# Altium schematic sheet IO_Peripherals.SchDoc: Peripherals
size A4; Date: Not used; ApprovedBy: Not used; CheckedBy: Not used; Author: Not used; CompanyName: STMicroelectronics; DrawnBy: Not used; Engineer: Not used; Organization: Not used; Address1: Not used; Address2: Not used; Address3: Not used; Address4: Not used; Revision: Not used; SheetNumber: 7; SheetTotal: 8
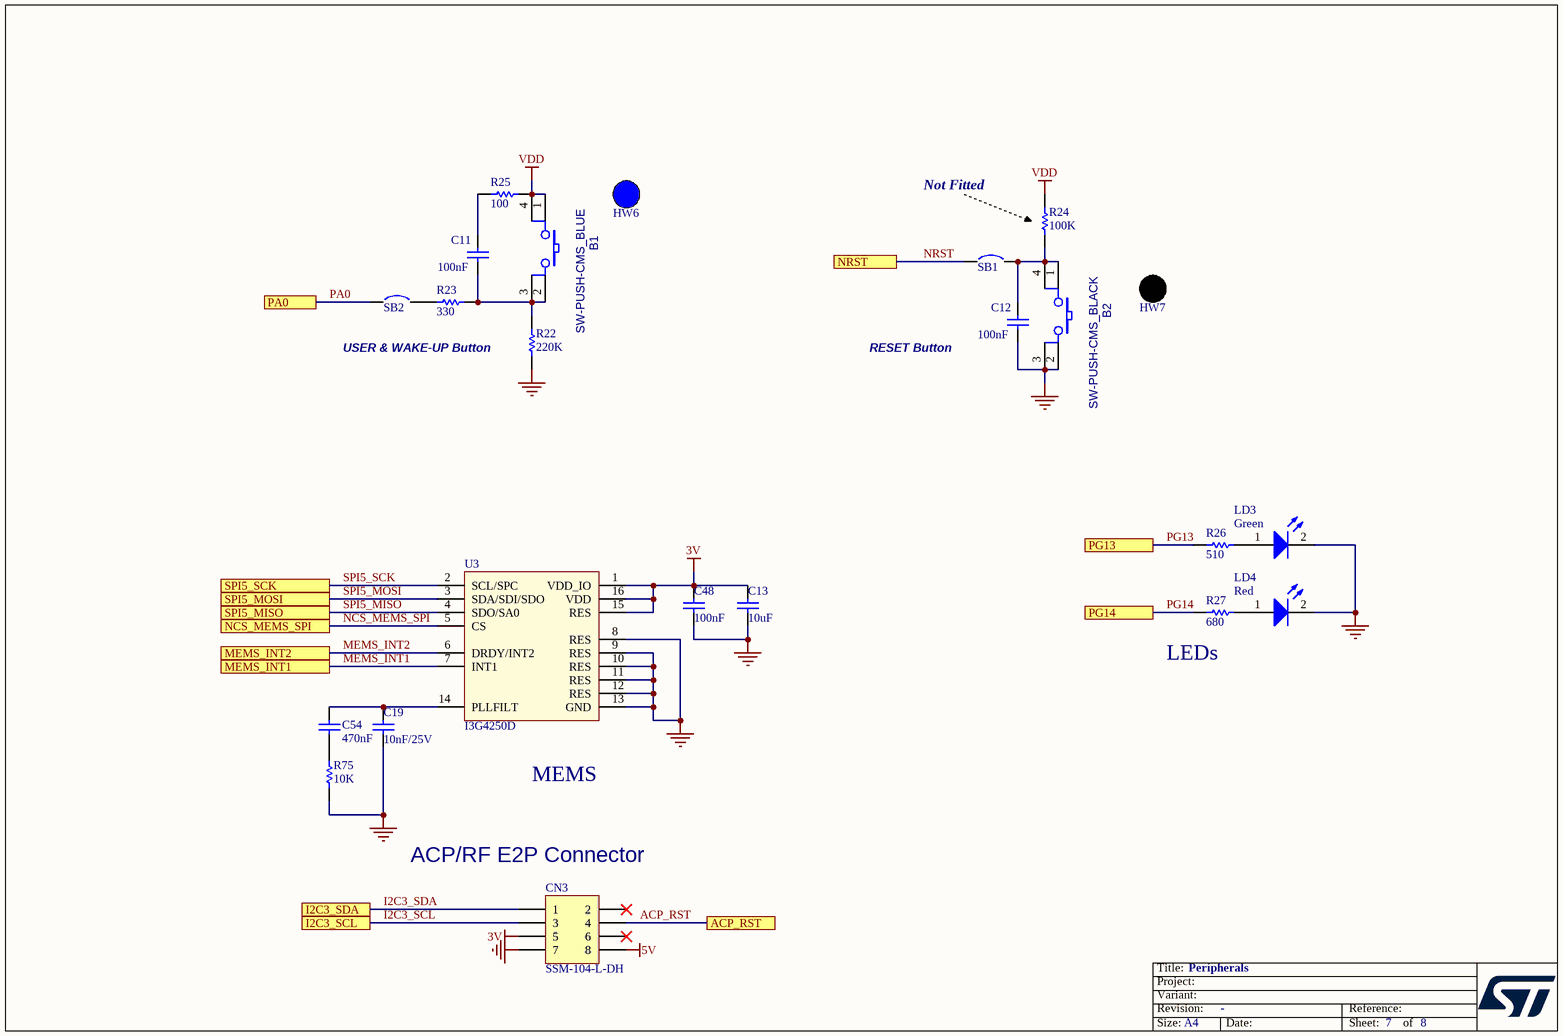
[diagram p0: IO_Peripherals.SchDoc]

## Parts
B1  SW-PUSH-CMS_BLUE  [BP1CMS]
B2  SW-PUSH-CMS_BLACK  [BP1CMS]
C11  100nF  [0402C]
C12  100nF  [0402C]
C13  10uF  [0603C]
C19  10nF/25V  [0603C]
C48  100nF  [0402C]
C54  value 470nF  [C0603]  (hidden comment: Capacitor)
CN3  SSM-104-L-DH  [SSM-104-L-DH]
HW6  BUTTON_HAT_BLUE  (value not drawn)  (mechanical)
HW7  BUTTON_HAT_BLACK  (value not drawn)  (mechanical)
LD3  Green  [0603D]
LD4  Red  [0603D]
R22  220K  [0402R]
R23  330  [0402R]
R24  100K  [0402R]
R25  100  [0402R]
R26  510  [0603R]
R27  680  [0603R]
R75  10K  [0402R]
SB1  Circuit Breaker  [JP2_SMD]  (value not drawn)
SB2  Circuit Breaker  [JP2_SMD]  (value not drawn)
U3  I3G4250D  [ICC_LGA16_4X4_P065_H1P1]

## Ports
ACP_RST, I2C3_SCL, I2C3_SDA, MEMS_INT1, MEMS_INT2, NCS_MEMS_SPI, NRST, PA0, PG13, PG14, SPI5_MISO, SPI5_MOSI, SPI5_SCK

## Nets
3V: C13.2 C48.2 CN3.5 U3.1(VDD_IO) U3.15(RES) U3.16(VDD)
5V: CN3.8
GND: B2.2 B2.3 C12.1 C13.1 C19.1 C48.1 CN3.7 LD3.2(K) LD4.2(K) R22.1 R75.1 U3.8(RES) U3.9(RES) U3.10(RES) U3.11(RES) U3.12(RES) U3.13(GND)
VDD: B1.1 B1.4 R24.2 R25.2
ACP_RST: CN3.4 ; port ACP_RST
I2C3_SCL: CN3.3 ; port I2C3_SCL
I2C3_SDA: CN3.1 ; port I2C3_SDA
MEMS_INT1: U3.7(INT1) ; port MEMS_INT1
MEMS_INT2: U3.6(DRDY/INT2) ; port MEMS_INT2
NCS_MEMS_SPI: U3.5(CS) ; port NCS_MEMS_SPI
NRST: SB1.1 ; port NRST
PA0: SB2.1 ; port PA0
PG13: R26.1 ; port PG13
PG14: R27.1 ; port PG14
SPI5_MISO: U3.4(SDO/SA0) ; port SPI5_MISO
SPI5_MOSI: U3.3(SDA/SDI/SDO) ; port SPI5_MOSI
SPI5_SCK: U3.2(SCL/SPC) ; port SPI5_SCK
NetB1_2: B1.2 B1.3 C11.1 R22.2 R23.2
NetB2_1: B2.1 B2.4 C12.2 R24.1 SB1.2
NetC11_2: C11.2 R25.1
NetC19_2: C19.2 C54.2 U3.14(PLLFILT)
NetC54_1: C54.1 R75.2
NetLD3_1: LD3.1(A) R26.2
NetLD4_1: LD4.1(A) R27.2
NetR23_1: R23.1 SB2.2

Not connected (* = marked no-connect by the designer): CN3 2* 6*

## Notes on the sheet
- Not Fitted
- USER & WAKE-UP Button
- RESET Button
- (near R27) LEDs
- MEMS
- (near CN3) ACP/RF E2P Connector

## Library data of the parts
B1 = SW-PUSH-CMS_BLUE: Non-Open Push-Button 0.1A 24V; Manuf_2: FARNELL; Manuf_Part_2: 535-930; Manuf_1: wealthmetal; Manuf_Part_1: TD0341X-G01-BLU; Ref St: 9180120
B2 = SW-PUSH-CMS_BLACK: Non-Open Push-Button 0.1A 24V; Manuf_2: FARNELL; Manuf_Part_2: 535-930; Manuf_1: wealthmetal; Manuf_Part_1: TD0341X-G01-BLA; Ref St: 9180120
C11 C12 C48 = Capacitor_ST: Capacitor 0402 / 0603 / 0805
C13 C19 = CAP: Capacitor; Value: 100nF
C54 = MCD-01006: Capacitor, MLCC, 470nF, 16V, X7R, 10%, 0603, T=0.8mm; Manufacturer_Part_Number: CC0603KRX7R7BB474; Manufacturer: YAGEO; Alternate_Manufacturer_Part_Number: GCM155R71C104KA55D; Alternate_Manufacturer: MURATA; BMS_Part_Number: 9142003; Provided_By: SUBCO
CN3 = SSM-104-L-DH: Header, 5-Pin, Dual row
LD3 LD4 = LED2: Typical RED, GREEN, YELLOW, AMBER GaAs LED
R22-R27 = Resistor_ST: Resistor 0402 / 0603 / 0805; Value: 10K
R75 = Resistor_ST: Resistor 0402 / 0603 / 0805
SB1 SB2 = Circuit Breaker: Solder: YES
U3 = MCD-01963: MEMS motion sensor: 3-axis digital output gyroscope LG4-16 4x4mm; Part_Type: IC; Manufacturer: STMICROELECTRONICS; ECCN_US: EAR99; ECCN_EU: NEC; Provided_By: SUBCO with ST control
